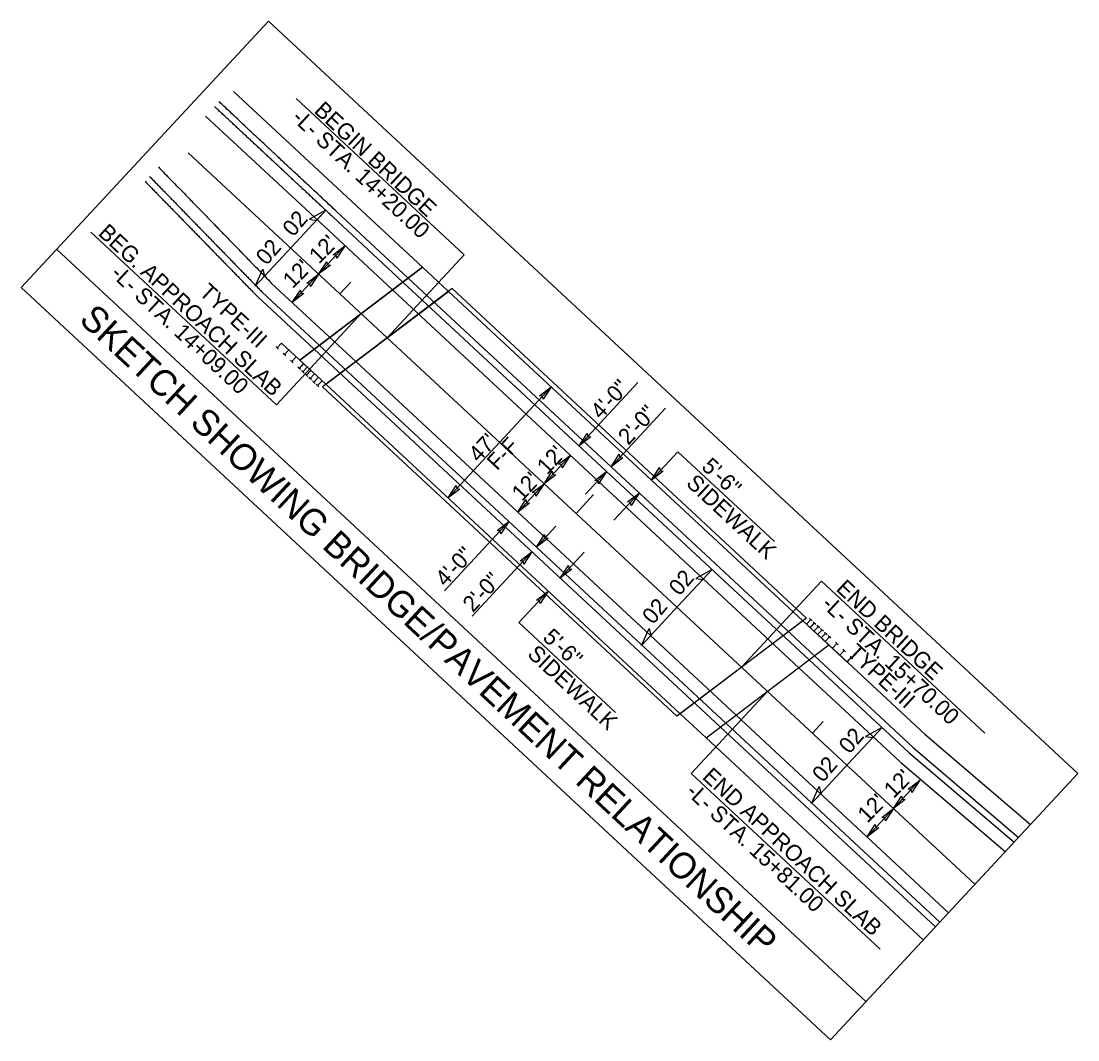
# Model space of a CAD drawing. Extents: x 2057696 to 2061410, y 685900 to 689434.
# Drawn here: x 2061082.7 to 2061410.4, y 687120.8 to 687436.6 of the extents above; entities that cross this region are included whole.
import ezdxf

# ---------------------------------------------------------------- set-up
doc = ezdxf.new("R2010")
doc.units = 0
for name, color, linetype in [('Old_Level_1', 7, 'Continuous'), ('Old_Level_63', 7, 'Continuous'), ('Prop Approach Slab', 7, 'Continuous'), ('Prop EOT', 7, 'Continuous'), ('Prop Guardrail', 7, 'Continuous'), ('Prop Horizontal Alignment', 7, 'Continuous'), ('Prop Structure Anchor Unit CELL', 7, 'Continuous'), ('Prop Vertical Profile Grade', 7, 'Continuous'), ('Prop Vertical Profile Grade Label', 7, 'Continuous'), ('Prop VPI Label', 7, 'Continuous'), ('Sheet Block Revision CELL', 7, 'Continuous'), ('Sheet Data Field CELL', 7, 'Continuous'), ('Sheet DOT Grid CELL', 7, 'Continuous'), ('Sheet Profile CELL', 7, 'Continuous'), ('Sheet Profile Grid Minor CELL', 7, 'Continuous'), ('Sheet Sticker Incomplete CELL', 7, 'Continuous')]:
    doc.layers.add(name, color=color, linetype=linetype)

msp = doc.modelspace()

# ---------------------------------------------------------------- linework, layer by layer
at = {"layer": 'Old_Level_1'}
for p, q in [((2061181.54, 687352.02), (2061184.94, 687355.68)), ((2061328.03, 687215.86), (2061331.43, 687219.52))]:
    msp.add_line(p, q, dxfattribs=at)
at = {"layer": 'Old_Level_63'}
for p, q in [((2061148.59, 687414.73), (2061207.16, 687360.29)), ((2061202.71, 687356.92), (2061328.69, 687239.82)), ((2061173.55, 687334.87), (2061299.54, 687217.77)), ((2061330.11, 687246.01), (2061363.07, 687215.37)), ((2061295.08, 687214.4), (2061362.44, 687151.79)), ((2061362.87, 687215.56), (2061395.7, 687187.58))]:
    msp.add_line(p, q, dxfattribs=at)
at = {"layer": 'Prop Approach Slab'}
for p, q in [((2061093.73, 687365.85), (2061344.64, 687132.64)), ((2061166.79, 687349.35), (2061183.13, 687366.93)), ((2061345, 687183.72), (2061361.33, 687201.29))]:
    msp.add_line(p, q, dxfattribs=at)
msp.add_lwpolyline([(2061333.63, 687120.8), (2061082.72, 687354.01), (2061159.45, 687436.56), (2061410.35, 687203.34)], close=True, dxfattribs=at)
at = {"layer": 'Prop EOT'}
for points in [[(2061179.5, 687364.16), (2061183.13, 687366.93), (2061180.64, 687363.07), (2061180.44, 687364.03)], [(2061178.59, 687360.91), (2061174.96, 687358.14), (2061177.45, 687362), (2061177.65, 687361.03)], [(2061171.33, 687355.37), (2061174.96, 687358.14), (2061172.46, 687354.28), (2061172.27, 687355.24)], [(2061170.42, 687352.12), (2061166.79, 687349.35), (2061169.29, 687353.21), (2061169.48, 687352.24)], [(2061243.44, 687320.43), (2061247.07, 687323.19), (2061244.58, 687319.34), (2061244.38, 687320.3)], [(2061259.36, 687307.67), (2061255.73, 687304.91), (2061258.23, 687308.76), (2061258.42, 687307.8)], [(2061249.38, 687299.21), (2061253.01, 687301.98), (2061250.51, 687298.12), (2061250.32, 687299.08)], [(2061269.25, 687301.21), (2061265.62, 687298.45), (2061268.11, 687302.3), (2061268.31, 687301.34)], [(2061248.47, 687295.95), (2061244.84, 687293.19), (2061247.33, 687297.05), (2061247.53, 687296.08)], [(2061260.63, 687294.21), (2061264.26, 687296.98), (2061261.76, 687293.12), (2061261.57, 687294.09)], [(2061281.77, 687297.09), (2061278.13, 687294.32), (2061280.63, 687298.18), (2061280.82, 687297.22)], [(2061218.7, 687291.54), (2061215.07, 687288.77), (2061217.57, 687292.63), (2061217.76, 687291.66)], [(2061241.21, 687290.42), (2061244.84, 687293.19), (2061242.34, 687289.33), (2061242.15, 687290.29)], [(2061270.76, 687287.53), (2061274.39, 687290.29), (2061271.89, 687286.43), (2061271.7, 687287.4)], [(2061240.3, 687287.17), (2061236.67, 687284.4), (2061239.16, 687288.26), (2061239.36, 687287.29)], [(2061230.31, 687278.7), (2061233.94, 687281.47), (2061231.45, 687277.61), (2061231.26, 687278.57)], [(2061246.1, 687276.31), (2061242.47, 687273.54), (2061244.97, 687277.4), (2061245.16, 687276.43)], [(2061237.48, 687269.31), (2061241.11, 687272.08), (2061238.62, 687268.22), (2061238.42, 687269.18)], [(2061253.51, 687266.69), (2061249.88, 687263.92), (2061252.38, 687267.78), (2061252.57, 687266.82)], [(2061242.5, 687257.13), (2061246.14, 687259.9), (2061243.64, 687256.04), (2061243.45, 687257)], [(2061357.7, 687198.52), (2061361.33, 687201.29), (2061358.84, 687197.43), (2061358.64, 687198.4)], [(2061356.79, 687195.27), (2061353.16, 687192.5), (2061355.66, 687196.36), (2061355.85, 687195.4)], [(2061349.53, 687189.73), (2061353.16, 687192.5), (2061350.67, 687188.64), (2061350.47, 687189.61)], [(2061348.63, 687186.48), (2061345, 687183.72), (2061347.49, 687187.57), (2061347.69, 687186.61)]]:
    msp.add_lwpolyline(points, close=True, dxfattribs=at)
at = {"layer": 'Prop Guardrail'}
msp.add_line((2061134.52, 687395.73), (2061378.44, 687169.01), dxfattribs=at)
at = {"layer": 'Prop Horizontal Alignment'}
for p, q in [((2061216.33, 687353.64), (2061176.11, 687323.22)), ((2061215.22, 687352.8), (2061325.09, 687250.68)), ((2061216.33, 687353.64), (2061326.2, 687251.52)), ((2061176.11, 687323.22), (2061285.98, 687221.1)), ((2061177.15, 687324.01), (2061287.02, 687221.89)), ((2061326.2, 687251.52), (2061285.98, 687221.1))]:
    msp.add_line(p, q, dxfattribs=at)
at = {"layer": 'Prop Structure Anchor Unit CELL'}
for p, q in [((2061169.1, 687331.5), (2061207.16, 687360.29)), ((2061295.08, 687214.4), (2061333.15, 687243.19))]:
    msp.add_line(p, q, dxfattribs=at)
at = {"layer": 'Prop Vertical Profile Grade'}
for p, q in [((2061176.52, 687373.07), (2061139.9, 687407.11)), ((2061176.52, 687373.07), (2061197.85, 687353.24)), ((2061160.18, 687355.49), (2061186.47, 687331.06)), ((2061197.85, 687353.24), (2061323.83, 687236.15)), ((2061186.47, 687331.06), (2061304.39, 687221.45)), ((2061323.83, 687236.15), (2061355.24, 687206.95)), ((2061304.39, 687221.45), (2061370.27, 687160.22)), ((2061355.37, 687206.83), (2061387.86, 687179.15))]:
    msp.add_line(p, q, dxfattribs=at)
msp.add_open_spline([(2061125.26, 687391.36), (2061137.05, 687379.26), (2061148.69, 687367.3), (2061160.33, 687355.35)], degree=2, dxfattribs=at)
at = {"layer": 'Prop Vertical Profile Grade Label'}
for p, q in [((2061162.48, 687334.92), (2061161.64, 687335.7)), ((2061163.42, 687336.78), (2061162.06, 687335.31)), ((2061177.15, 687324.01), (2061163.42, 687336.78)), ((2061165.71, 687334.65), (2061164.35, 687333.19)), ((2061164.77, 687332.8), (2061163.93, 687333.58)), ((2061167.06, 687330.67), (2061166.22, 687331.45)), ((2061168, 687332.52), (2061166.64, 687331.06)), ((2061169.34, 687328.54), (2061168.51, 687329.32)), ((2061170.29, 687330.4), (2061168.93, 687328.93)), ((2061170.49, 687327.48), (2061169.65, 687328.26)), ((2061171.43, 687329.33), (2061170.07, 687327.87)), ((2061172.58, 687328.27), (2061171.21, 687326.8)), ((2061171.63, 687326.41), (2061170.79, 687327.19)), ((2061172.78, 687325.35), (2061171.94, 687326.13)), ((2061173.72, 687327.2), (2061172.36, 687325.74)), ((2061173.92, 687324.29), (2061173.08, 687325.07)), ((2061174.86, 687326.14), (2061173.5, 687324.68)), ((2061176.01, 687325.08), (2061174.65, 687323.61)), ((2061175.07, 687323.22), (2061174.23, 687324)), ((2061325.09, 687250.68), (2061338.82, 687237.91)), ((2061326.24, 687249.61), (2061327.6, 687251.08)), ((2061327.18, 687251.47), (2061328.02, 687250.69)), ((2061327.38, 687248.55), (2061328.74, 687250.01)), ((2061328.32, 687250.4), (2061329.16, 687249.62)), ((2061329.47, 687249.34), (2061330.31, 687248.56)), ((2061328.52, 687247.49), (2061329.89, 687248.95)), ((2061329.67, 687246.42), (2061331.03, 687247.89)), ((2061330.61, 687248.28), (2061331.45, 687247.5)), ((2061330.81, 687245.36), (2061332.17, 687246.82)), ((2061331.76, 687247.21), (2061332.59, 687246.43)), ((2061332.9, 687246.15), (2061333.74, 687245.37)), ((2061331.96, 687244.29), (2061333.32, 687245.76)), ((2061334.25, 687242.17), (2061335.61, 687243.63)), ((2061335.19, 687244.02), (2061336.03, 687243.24)), ((2061336.54, 687240.04), (2061337.9, 687241.5)), ((2061337.48, 687241.89), (2061338.32, 687241.11)), ((2061339.77, 687239.77), (2061340.61, 687238.99)), ((2061338.82, 687237.91), (2061340.19, 687239.38))]:
    msp.add_line(p, q, dxfattribs=at)
at = {"layer": 'Prop VPI Label'}
for p, q in [((2061180.61, 687377.46), (2061202.71, 687356.92)), ((2061156.1, 687351.09), (2061173.55, 687334.87)), ((2061328.69, 687239.82), (2061359.3, 687211.37)), ((2061299.54, 687217.77), (2061366.19, 687155.82)), ((2061359.3, 687211.37), (2061391.95, 687183.54))]:
    msp.add_line(p, q, dxfattribs=at)
msp.add_open_spline([(2061180.61, 687377.46), (2061168.42, 687388.82), (2061156.22, 687400.18), (2061144.08, 687411.61)], degree=2, dxfattribs=at)
msp.add_spline([(2061121.13, 687386.92), (2061121.61, 687386.43), (2061122.08, 687385.95), (2061122.55, 687385.46), (2061123.02, 687384.98), (2061123.5, 687384.5), (2061123.97, 687384.01), (2061124.44, 687383.53), (2061124.91, 687383.04), (2061125.39, 687382.56), (2061125.86, 687382.07), (2061126.33, 687381.59), (2061126.8, 687381.11), (2061127.28, 687380.62), (2061127.75, 687380.14), (2061128.22, 687379.65), (2061128.69, 687379.17), (2061129.17, 687378.69), (2061129.64, 687378.2), (2061130.11, 687377.72), (2061130.58, 687377.23), (2061131.06, 687376.75), (2061131.53, 687376.27), (2061132, 687375.78), (2061132.47, 687375.3), (2061132.95, 687374.81), (2061133.42, 687374.33), (2061133.89, 687373.85), (2061134.36, 687373.36), (2061134.84, 687372.88), (2061135.31, 687372.39), (2061135.78, 687371.91), (2061136.25, 687371.42), (2061136.73, 687370.94), (2061137.2, 687370.46), (2061137.67, 687369.97), (2061138.14, 687369.49), (2061138.62, 687369), (2061139.09, 687368.52), (2061139.56, 687368.04), (2061140.03, 687367.55), (2061140.51, 687367.07), (2061140.98, 687366.58), (2061141.45, 687366.1), (2061141.92, 687365.62), (2061142.4, 687365.13), (2061142.87, 687364.65), (2061143.34, 687364.16), (2061143.81, 687363.68), (2061144.29, 687363.19), (2061144.76, 687362.71), (2061145.23, 687362.23), (2061145.7, 687361.74), (2061146.18, 687361.26), (2061146.65, 687360.77), (2061147.12, 687360.29), (2061147.59, 687359.81), (2061148.07, 687359.32), (2061148.54, 687358.84), (2061149.01, 687358.35), (2061149.48, 687357.87), (2061149.96, 687357.39), (2061150.43, 687356.9), (2061150.9, 687356.42), (2061151.37, 687355.93), (2061151.85, 687355.45), (2061152.32, 687354.96), (2061152.79, 687354.48), (2061153.26, 687354), (2061153.74, 687353.51), (2061154.21, 687353.03), (2061154.68, 687352.54), (2061155.15, 687352.06), (2061156.1, 687351.09)], degree=3, dxfattribs=at)
at = {"layer": 'Sheet Block Revision CELL'}
for p, q in [((2061220.07, 687364.11), (2061167.96, 687412.55)), ((2061161.9, 687317.67), (2061104.36, 687371.15)), ((2061196.19, 687338.41), (2061220.07, 687364.11)), ((2061188.13, 687345.89), (2061161.9, 687317.67)), ((2061215.07, 687288.77), (2061247.07, 687323.19)), ((2061255.73, 687304.91), (2061273.96, 687324.52)), ((2061265.62, 687298.45), (2061282.49, 687316.6)), ((2061244.84, 687293.19), (2061253.01, 687301.98)), ((2061278.13, 687294.32), (2061286.29, 687303.1)), ((2061286.29, 687303.1), (2061316.25, 687275.26)), ((2061257.75, 687289.98), (2061264.26, 687296.98)), ((2061236.67, 687284.4), (2061244.84, 687293.19)), ((2061266.52, 687281.83), (2061274.39, 687290.29)), ((2061214.01, 687260.02), (2061233.94, 687281.47)), ((2061242.47, 687273.54), (2061248.54, 687280.07)), ((2061222.54, 687252.09), (2061241.11, 687272.08)), ((2061249.88, 687263.92), (2061257.31, 687271.92)), ((2061306.06, 687236.29), (2061330.88, 687262.99)), ((2061330.88, 687262.99), (2061381.55, 687215.9)), ((2061237.08, 687250.15), (2061246.14, 687259.9)), ((2061237.08, 687250.15), (2061267.04, 687222.31)), ((2061314.11, 687228.8), (2061290.48, 687203.37)), ((2061290.48, 687203.37), (2061349.1, 687148.88))]:
    msp.add_line(p, q, dxfattribs=at)
at = {"layer": 'Sheet Data Field CELL'}
msp.add_line((2061254.78, 687283.94), (2061260.23, 687289.8), dxfattribs=at)
at = {"layer": 'Sheet DOT Grid CELL'}
for points in [[(2061215.22, 687352.8), (2061207.16, 687360.29), (2061169.1, 687331.5), (2061177.15, 687324.01)], [(2061287.03, 687221.89), (2061295.08, 687214.4), (2061333.15, 687243.19), (2061325.09, 687250.68)]]:
    msp.add_lwpolyline(points, close=True, dxfattribs=at)
at = {"layer": 'Sheet Profile Grid Minor CELL'}
for p, q in [((2061166.69, 687366.64), (2061177.18, 687377.92)), ((2061155.3, 687354.38), (2061166.69, 687366.64)), ((2061286.46, 687255.32), (2061296.95, 687266.6)), ((2061275.07, 687243.05), (2061286.46, 687255.32)), ((2061339.17, 687206.33), (2061349.65, 687217.61)), ((2061327.77, 687194.07), (2061339.17, 687206.33))]:
    msp.add_line(p, q, dxfattribs=at)
for points in [[(2061177.18, 687377.92), (2061172.09, 687375.14), (2061174.29, 687374.81)], [(2061155.3, 687354.38), (2061157.7, 687359.65), (2061158.18, 687357.48)], [(2061296.95, 687266.6), (2061291.86, 687263.82), (2061294.06, 687263.49)], [(2061275.07, 687243.05), (2061277.47, 687248.33), (2061277.95, 687246.16)], [(2061349.65, 687217.61), (2061344.56, 687214.83), (2061346.76, 687214.5)], [(2061327.77, 687194.07), (2061330.17, 687199.35), (2061330.66, 687197.17)]]:
    msp.add_lwpolyline(points, close=True, dxfattribs=at)
at = {"layer": 'Sheet Sticker Incomplete CELL'}
for p, q in [((2061179.25, 687376), (2061201.09, 687355.69)), ((2061201.09, 687355.69), (2061327.07, 687238.59)), ((2061157.46, 687352.56), (2061175.17, 687336.1)), ((2061175.17, 687336.1), (2061301.16, 687219)), ((2061327.07, 687238.59), (2061357.97, 687209.88)), ((2061301.16, 687219), (2061367.55, 687157.29)), ((2061357.97, 687209.88), (2061390.59, 687182.08))]:
    msp.add_line(p, q, dxfattribs=at)
for points in [[(2061179.25, 687376), (2061178.75, 687376.46), (2061178.26, 687376.92), (2061177.76, 687377.38), (2061177.27, 687377.84), (2061176.77, 687378.3), (2061176.28, 687378.76), (2061175.79, 687379.22), (2061175.29, 687379.68), (2061174.8, 687380.14), (2061174.3, 687380.6), (2061173.81, 687381.06), (2061173.31, 687381.52), (2061172.82, 687381.98), (2061172.33, 687382.44), (2061171.83, 687382.91), (2061171.34, 687383.37), (2061170.84, 687383.83), (2061170.35, 687384.29), (2061169.85, 687384.75), (2061169.36, 687385.21), (2061168.87, 687385.67), (2061168.37, 687386.13), (2061167.88, 687386.59), (2061167.38, 687387.05), (2061166.89, 687387.51), (2061166.39, 687387.97), (2061165.9, 687388.43), (2061165.41, 687388.89), (2061164.91, 687389.35), (2061164.42, 687389.81), (2061163.92, 687390.28), (2061163.43, 687390.74), (2061162.93, 687391.2), (2061162.44, 687391.66), (2061161.95, 687392.12), (2061161.45, 687392.58), (2061160.96, 687393.04), (2061160.46, 687393.5), (2061159.97, 687393.96), (2061159.47, 687394.42), (2061158.98, 687394.88), (2061158.48, 687395.34), (2061157.99, 687395.8), (2061157.5, 687396.26), (2061157, 687396.72), (2061156.51, 687397.19), (2061156.01, 687397.65), (2061155.52, 687398.11), (2061155.02, 687398.57), (2061154.53, 687399.03), (2061154.04, 687399.49), (2061153.54, 687399.95), (2061153.05, 687400.41), (2061152.55, 687400.87), (2061152.06, 687401.33), (2061151.56, 687401.79), (2061151.07, 687402.25), (2061150.58, 687402.71), (2061150.08, 687403.17), (2061149.59, 687403.63), (2061149.09, 687404.09), (2061148.6, 687404.56), (2061148.1, 687405.02), (2061147.61, 687405.48), (2061147.12, 687405.94), (2061146.62, 687406.4), (2061146.13, 687406.86), (2061145.63, 687407.32), (2061145.14, 687407.78), (2061144.64, 687408.24), (2061144.15, 687408.7), (2061143.66, 687409.16), (2061142.67, 687410.08)], [(2061122.54, 687388.43), (2061123.01, 687387.94), (2061123.48, 687387.46), (2061123.95, 687386.97), (2061124.43, 687386.49), (2061124.9, 687386), (2061125.37, 687385.52), (2061125.84, 687385.03), (2061126.31, 687384.55), (2061126.79, 687384.06), (2061127.26, 687383.58), (2061127.73, 687383.1), (2061128.2, 687382.61), (2061128.67, 687382.13), (2061129.15, 687381.64), (2061129.62, 687381.16), (2061130.09, 687380.67), (2061130.56, 687380.19), (2061131.03, 687379.7), (2061131.5, 687379.22), (2061131.98, 687378.73), (2061132.45, 687378.25), (2061132.92, 687377.76), (2061133.39, 687377.28), (2061133.86, 687376.79), (2061134.34, 687376.31), (2061134.81, 687375.82), (2061135.28, 687375.34), (2061135.75, 687374.85), (2061136.22, 687374.37), (2061136.7, 687373.89), (2061137.17, 687373.4), (2061137.64, 687372.92), (2061138.11, 687372.43), (2061138.58, 687371.95), (2061139.06, 687371.46), (2061139.53, 687370.98), (2061140, 687370.49), (2061140.47, 687370.01), (2061140.94, 687369.52), (2061141.42, 687369.04), (2061141.89, 687368.55), (2061142.36, 687368.07), (2061142.83, 687367.58), (2061143.3, 687367.1), (2061143.77, 687366.61), (2061144.25, 687366.13), (2061144.72, 687365.64), (2061145.19, 687365.16), (2061145.66, 687364.68), (2061146.13, 687364.19), (2061146.61, 687363.71), (2061147.08, 687363.22), (2061147.55, 687362.74), (2061148.02, 687362.25), (2061148.49, 687361.77), (2061148.97, 687361.28), (2061149.44, 687360.8), (2061149.91, 687360.31), (2061150.38, 687359.83), (2061150.85, 687359.34), (2061151.33, 687358.86), (2061151.8, 687358.37), (2061152.27, 687357.89), (2061152.74, 687357.4), (2061153.21, 687356.92), (2061153.69, 687356.43), (2061154.16, 687355.95), (2061154.63, 687355.47), (2061155.1, 687354.98), (2061155.57, 687354.5), (2061156.04, 687354.01), (2061156.52, 687353.53), (2061157.46, 687352.56)]]:
    msp.add_spline(points, degree=3, dxfattribs=at)

# ---------------------------------------------------------------- texts
at = {"layer": 'Prop Approach Slab'}
for p in [(2061175.02, 687361.05), (2061166.88, 687353.43), (2061353.23, 687195.41), (2061345.09, 687187.8)]:
    msp.add_text("12'", height=5, rotation=45.193, dxfattribs=at).set_placement(p)
at = {"layer": 'Sheet Block Revision CELL'}
for s, height, rotation, p in [('BEGIN BRIDGE', 5, 317.0934, (2061173.25, 687408.45)), ('-L- STA. 14+20.00', 5, 317.0934, (2061166.35, 687406.12)), ('BEG. APPROACH SLAB', 5, 317.0934, (2061106.32, 687370.51)), ('-L- STA. 14+09.00', 5, 317.0934, (2061110.18, 687357.82)), ('TYPE-III', 5, 317.0934, (2061137.61, 687352.06)), ('SKETCH SHOWING BRIDGE/PAVEMENT RELATIONSHIP', 8.1, 317.0934, (2061100.33, 687343.55)), ('4\'-0"', 5, 47.0934, (2061262.46, 687312.83)), ('2\'-0"', 5, 47.0934, (2061270.98, 687304.9)), ("47'", 5, 47.0934, (2061224.61, 687299.52)), ('F-F', 5, 47.0934, (2061230.3, 687297.03)), ("12'", 5, 47.0934, (2061245.82, 687295.71)), ('5\'-6"', 5, 317.0934, (2061293.37, 687298.05)), ("12'", 5, 47.0934, (2061238, 687287.49)), ('SIDEWALK', 5, 317.0934, (2061288.6, 687292.92)), ('4\'-0"', 5, 47.0934, (2061214.27, 687260.99)), ('2\'-0"', 5, 47.0934, (2061222.8, 687253.06)), ('END BRIDGE', 5, 317.0934, (2061335.08, 687260.27)), ('-L- STA. 15+70.00', 5, 317.0934, (2061330.54, 687255.39)), ('5\'-6"', 5, 317.0934, (2061244.15, 687245.1)), ('SIDEWALK', 5, 317.0934, (2061239.39, 687239.97)), ('TYPE-III', 5, 317.0934, (2061338.53, 687240.35)), ('END APPROACH SLAB', 5, 317.0934, (2061293.64, 687201.98)), ('-L- STA. 15+81.00', 5, 317.0934, (2061288.53, 687197.26))]:
    msp.add_text(s, height=height, rotation=rotation, dxfattribs=at).set_placement(p)
at = {"layer": 'Sheet Profile CELL'}
for p in [(2061167.08, 687369.47), (2061158.84, 687360.61), (2061286.85, 687258.15), (2061278.61, 687249.28), (2061339.55, 687209.16), (2061331.31, 687200.3)]:
    msp.add_text('02', height=5, rotation=49.3596, dxfattribs=at).set_placement(p)

doc.saveas('drawing.dxf')
